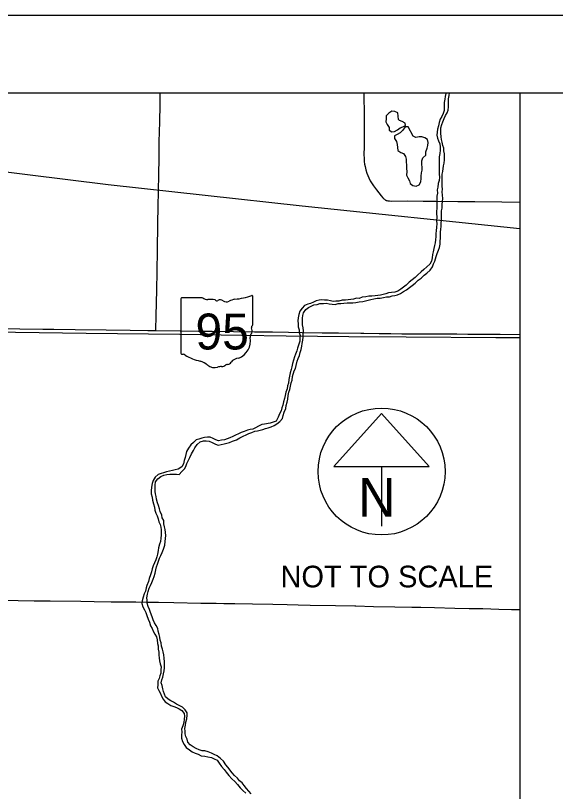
# Model space of a CAD drawing. Extents: x 0 to 680, y 0 to 440.
# Drawn here: x 401.8 to 471.5, y 339.7 to 440 of the extents above; entities that cross this region are included whole.
import ezdxf

# ---------------------------------------------------------------- set-up
doc = ezdxf.new("R2010")
doc.units = 0
for name, color, linetype in [('GM_X_County_Road', 7, 'Continuous'), ('GM_X_Major_River', 7, 'Continuous'), ('GM_X_Minor_Lake', 7, 'Continuous'), ('GM_X_State_Location', 7, 'Continuous'), ('GM_X_State_Route', 7, 'Continuous'), ('GM_X_State_Shield', 7, 'Continuous'), ('GM_X_Township_Road', 7, 'Continuous'), ('RD_X_RR_2', 7, 'Continuous'), ('SH_Border', 7, 'Continuous'), ('SH_Cut_Line', 7, 'Continuous'), ('SH_Masking', 7, 'Continuous'), ('SH_Text', 7, 'Continuous')]:
    doc.layers.add(name, color=color, linetype=linetype)

msp = doc.modelspace()

# ---------------------------------------------------------------- linework, layer by layer
at = {"layer": 'GM_X_County_Road'}
msp.add_line((454.58, 416.02), (455.63, 416.01), dxfattribs=at)
for points in [[(446.79, 430), (446.79, 429.44), (446.8, 427.47), (446.8, 426.16), (446.8, 425.17), (446.8, 423.09), (446.79, 422), (446.8, 421.55)], [(446.8, 421.55), (446.8, 421.43), (446.82, 421.13), (446.87, 420.81), (446.93, 420.49), (447.03, 420.06), (447.16, 419.64), (447.27, 419.34), (447.4, 419.04), (447.6, 418.65), (447.76, 418.37), (448, 418.01), (448.39, 417.48), (449, 416.71), (449.21, 416.46), (449.37, 416.31), (449.43, 416.25), (449.48, 416.21), (449.57, 416.16), (449.64, 416.13)], [(449.64, 416.13), (449.67, 416.12), (449.76, 416.08), (449.86, 416.06), (450.07, 416.04), (450.4, 416.03), (452.37, 416.04), (454.44, 416.02), (454.58, 416.02)], [(455.63, 416.01), (456.08, 416), (458.93, 415.98), (461.11, 415.95), (464.61, 415.91), (466.92, 415.89)], [(396.22, 364.49), (402.12, 364.41), (404.2, 364.39), (406.27, 364.36), (410.21, 364.32), (411.96, 364.29), (414.14, 364.26), (417.31, 364.23), (418.84, 364.21), (420.27, 364.18), (422.23, 364.16), (425.73, 364.09), (426.93, 364.07), (427.7, 364.05), (428.68, 364.04), (430.1, 364.01), (432.4, 363.97), (435.02, 363.92), (436.88, 363.88), (438.3, 363.85), (439.83, 363.81), (443.11, 363.75), (445.62, 363.71), (445.74, 363.71)], [(445.74, 363.71), (448.03, 363.66), (450.76, 363.61), (452.95, 363.56), (454.15, 363.54), (455.9, 363.5), (458.52, 363.44), (460.38, 363.4), (462.13, 363.36), (464.21, 363.3), (465.84, 363.27), (466.92, 363.26)]]:
    msp.add_lwpolyline(points, dxfattribs=at)
at = {"layer": 'GM_X_Major_River'}
for points in [[(457.38, 430), (457.36, 429.94), (457.27, 429.54), (457.24, 429.18), (457.14, 428.77), (457.16, 428.43), (457.15, 427.71), (457.01, 427.35), (456.83, 426.96), (456.64, 426.61), (456.5, 426.16), (456.4, 425.74), (456.3, 425.31), (456.24, 424.91), (456.22, 424.54), (456.28, 424.16), (456.43, 423.81), (456.6, 423.42), (456.63, 423.04), (456.64, 422.62), (456.58, 422.16)], [(457.06, 420.59), (457.13, 420.93), (457.18, 421.36), (457.18, 421.75), (457.18, 422.13), (457.12, 422.52), (457.12, 422.87), (456.97, 423.22), (456.91, 423.65), (456.82, 423.99), (456.76, 424.34), (456.71, 424.81), (456.71, 425.14), (456.71, 425.48), (456.84, 425.9), (456.98, 426.25), (457.16, 426.68), (457.34, 427.08), (457.52, 427.44), (457.66, 427.78), (457.7, 428.18), (457.7, 428.54), (457.69, 428.88), (457.71, 429.25), (457.78, 429.68), (457.85, 430)], [(456.58, 422.16), (456.5, 421.76), (456.51, 421.41), (456.48, 421.04), (456.5, 420.7), (456.52, 420.25), (456.49, 419.85), (456.52, 419.48), (456.54, 419.12), (456.48, 418.7), (456.37, 418.3), (456.33, 417.84), (456.26, 417.47), (456.27, 417.04), (456.21, 416.67), (456.21, 416.31), (456.19, 415.89), (456.19, 415.45), (456.19, 415.08), (456.15, 414.73), (456.17, 414.4), (456.18, 413.94), (456.17, 413.45), (456.2, 413.08), (456.15, 412.65), (456.13, 412.18), (456.09, 411.84), (456.07, 411.44), (456.03, 411.02), (456, 410.65), (455.9, 410.28), (455.82, 409.88), (455.72, 409.47), (455.64, 409.1), (455.6, 408.67), (455.5, 408.28), (455.28, 407.89), (454.91, 407.51), (454.53, 407.18), (454.16, 406.87), (453.72, 406.46), (453.39, 406.16), (453.02, 405.83), (452.64, 405.54), (452.22, 405.15), (451.89, 404.89), (451.54, 404.64), (451.15, 404.38), (450.79, 404.26), (450.33, 404.22), (449.95, 404.18), (449.61, 404.04), (449.26, 403.95), (448.93, 403.87), (448.58, 403.81), (448.24, 403.77), (447.81, 403.75), (447.44, 403.74), (447.02, 403.64), (446.57, 403.59), (446.17, 403.43), (445.82, 403.46), (445.45, 403.35), (444.75, 403.25), (444.41, 403.22), (443.97, 403.2), (443.55, 403.11), (443.17, 403.09), (442.82, 403.07), (442.46, 403.13), (442.1, 403.2), (441.71, 403.24), (441.33, 403.26), (440.99, 403.24), (440.61, 403.12), (440.28, 402.98), (439.88, 402.8), (439.53, 402.7), (439.13, 402.52), (438.83, 402.18), (438.52, 401.8), (438.37, 401.36), (438.3, 400.93), (438.24, 400.57), (438.28, 400.17), (438.31, 399.79), (438.41, 399.38), (438.44, 399.04), (438.53, 398.66), (438.5, 398.3), (438.49, 397.93), (438.4, 397.54), (438.22, 397.04), (438.1, 396.68), (437.93, 396.23), (437.81, 395.88), (437.7, 395.45), (437.58, 395.03), (437.46, 394.62), (437.38, 394.28), (437.27, 393.83)], [(437.02, 390.89), (437.1, 391.33), (437.23, 391.69), (437.29, 392.12), (437.39, 392.56), (437.5, 392.9), (437.58, 393.34), (437.78, 394.07), (437.94, 394.41), (438.04, 394.79), (438.17, 395.33), (438.29, 395.68), (438.45, 396.06), (438.56, 396.47), (438.66, 396.86), (438.75, 397.26), (438.79, 397.63), (438.91, 398.07), (438.95, 398.43), (438.95, 398.89), (438.97, 399.24), (438.92, 399.64), (438.87, 400.03), (438.84, 400.48), (438.86, 400.88), (438.91, 401.24), (438.99, 401.6), (439.28, 402), (439.63, 402.27), (439.98, 402.45), (440.32, 402.61), (440.73, 402.68), (441.1, 402.77), (441.55, 402.81), (441.9, 402.83), (442.28, 402.73), (442.7, 402.69), (443.08, 402.68), (443.46, 402.78), (443.8, 402.81), (444.17, 402.83), (444.63, 402.87), (444.97, 402.87), (445.37, 402.88), (445.73, 402.93), (446.15, 403.01), (446.63, 403.07), (446.99, 403.15), (447.32, 403.22), (447.68, 403.32), (448.08, 403.39), (448.48, 403.47), (448.9, 403.5), (449.3, 403.57), (449.72, 403.66), (450.07, 403.67), (450.43, 403.77), (450.77, 403.83), (451.14, 403.93), (451.5, 404.07), (451.88, 404.33), (452.27, 404.54), (452.66, 404.85), (453, 405.1), (453.4, 405.41), (453.81, 405.8), (454.17, 406.05), (454.57, 406.45), (454.92, 406.71), (455.32, 407.09), (455.64, 407.51), (455.78, 407.92), (455.94, 408.26), (456.1, 408.85), (456.24, 409.26), (456.4, 409.68), (456.54, 410.04), (456.65, 410.44), (456.67, 411.64), (456.68, 412.01), (456.7, 412.4), (456.78, 412.76), (456.76, 413.15), (456.81, 413.56), (456.81, 413.95), (456.81, 414.35), (456.81, 414.76), (456.87, 415.12), (456.88, 415.57), (456.93, 415.95), (456.97, 416.35), (456.95, 416.79), (456.91, 417.23), (456.95, 417.57), (456.91, 417.95), (456.89, 418.38), (456.89, 418.76), (456.87, 419.14), (456.89, 419.48), (456.97, 419.84), (457.06, 420.59)], [(437.27, 393.83), (437.18, 393.41), (437.09, 392.96), (437.03, 392.5), (436.93, 392.15), (436.87, 391.78), (436.72, 391.33), (436.63, 390.9), (436.52, 390.53), (436.42, 390.1), (436.3, 389.65), (436.19, 389.31), (436.08, 388.94), (435.89, 388.54), (435.73, 388.1), (435.47, 387.6), (435.07, 387.46), (434.66, 387.32), (433.94, 387.22), (433.58, 387.14), (433.16, 386.93), (432.8, 386.71), (432.45, 386.56), (432.11, 386.49), (431.73, 386.41), (431.34, 386.27), (430.95, 386.13), (430.59, 385.97), (430.19, 385.78), (429.84, 385.59), (429.49, 385.43), (429.13, 385.3), (428.78, 385.16), (428.39, 385.12), (428.02, 385.06), (427.65, 385.17), (427.3, 385.35), (426.92, 385.5), (426.58, 385.54), (426.2, 385.46), (425.87, 385.41), (425.48, 385.26), (425.12, 385.16), (424.77, 384.85), (424.43, 384.51), (424.12, 384.1), (423.88, 383.65), (423.77, 383.3), (423.68, 382.9), (423.57, 382.49), (423.47, 382.07), (423.26, 381.67), (422.79, 381.38), (422.39, 381.3), (422.06, 381.22), (421.68, 381.11), (421.3, 381.02), (420.92, 380.92), (420.59, 380.82), (420.23, 380.68), (419.84, 380.37), (419.59, 379.94), (419.45, 379.53), (419.36, 379.08), (419.3, 378.59), (419.33, 378.21), (419.43, 377.77), (419.49, 377.36), (419.62, 376.91), (419.76, 376.49), (419.79, 376.1), (419.92, 375.69), (420.09, 375.35), (420.21, 374.97), (420.31, 374.59), (420.47, 374.23), (420.54, 373.88), (420.6, 373.53), (420.61, 373.19), (420.6, 372.84), (420.56, 372.48), (420.5, 372.04), (420.4, 371.68), (420.27, 371.2), (420.21, 370.86), (420.11, 370.42), (420.04, 370.07), (419.91, 369.68), (419.75, 369.28), (419.57, 368.88), (419.43, 368.5), (419.34, 368.11), (419.22, 367.73), (419.07, 367.25), (418.98, 366.89), (418.77, 366.37), (418.68, 366.03), (418.57, 365.64), (418.4, 365.27), (418.26, 364.86), (418.15, 364.38)], [(419.97, 361.17), (419.73, 361.54), (419.57, 361.93), (419.43, 362.29), (419.23, 362.85), (419.1, 363.26), (418.94, 363.65), (418.81, 364.05), (418.78, 364.44), (418.75, 364.77), (418.84, 365.24), (418.94, 365.58), (419.07, 366.01), (419.23, 366.35), (419.39, 366.74), (419.57, 367.19), (419.7, 367.53), (419.82, 367.93), (419.92, 368.37), (420.02, 368.78), (420.12, 369.13), (420.24, 369.48), (420.4, 369.88), (420.55, 370.25), (420.73, 370.61), (420.91, 371.03), (421.06, 371.55), (421.12, 372.03), (421.16, 372.42), (421.19, 372.83), (421.17, 373.22), (421.1, 373.59), (421.02, 373.93), (420.96, 374.3), (420.96, 374.77), (420.75, 375.11), (420.67, 375.44), (420.49, 375.9), (420.39, 376.26), (420.27, 376.68), (420.13, 377.04), (420, 377.5), (419.95, 377.84), (419.85, 378.18), (419.81, 378.51), (419.81, 378.87), (419.83, 379.3), (419.88, 379.74), (420.16, 380.12), (420.58, 380.45), (420.96, 380.61), (421.33, 380.69), (421.73, 380.73), (422.58, 380.72), (422.94, 380.69), (423.28, 381.07), (423.62, 381.41), (423.8, 381.75), (423.92, 382.1), (424.14, 382.53), (424.31, 382.91), (424.5, 383.36), (424.76, 383.78), (424.97, 384.12), (425.27, 384.56), (425.65, 384.91), (426.05, 385.04), (426.42, 385.03), (426.79, 385.01), (427.19, 384.84), (427.61, 384.6), (427.97, 384.48), (428.33, 384.56), (428.73, 384.64), (429.1, 384.73), (429.44, 384.83), (429.8, 384.99), (430.32, 385.16), (430.77, 385.42), (431.21, 385.66), (431.58, 385.84), (431.92, 385.98), (432.33, 386.14), (432.7, 386.3), (433.04, 386.33), (433.38, 386.42), (433.72, 386.52), (434.09, 386.62), (434.42, 386.71), (434.82, 386.85), (435.18, 387.04), (435.55, 387.26), (435.94, 387.55), (436.26, 387.94), (436.36, 388.33), (436.49, 388.77), (436.7, 389.23), (436.74, 389.62), (436.87, 390.03), (436.97, 390.45), (437.02, 390.89)], [(418.15, 364.38), (418.1, 364.01), (418.24, 363.58), (418.46, 363.2), (418.62, 362.87), (418.77, 362.46), (418.92, 362.02), (419.1, 361.62), (419.24, 361.12), (419.42, 360.78), (419.59, 360.45), (419.79, 360.06), (420, 359.72), (420.1, 359.34), (420.13, 358.88), (420.2, 358.54), (420.23, 358.11), (420.29, 357.72), (420.31, 357.35), (420.36, 356.99), (420.39, 356.6), (420.49, 356.25), (420.6, 355.84), (420.56, 355.45), (420.55, 355.04), (420.44, 354.68), (420.34, 354.33), (420.17, 353.98), (420.15, 353.51), (420.13, 353.12), (420.29, 352.77), (420.51, 352.41), (420.65, 352.07), (420.86, 351.68), (421.1, 351.32), (421.46, 351.11), (421.85, 350.84), (422.22, 350.72), (422.57, 350.59), (422.94, 350.41), (423.28, 350.2), (423.58, 349.82), (423.63, 349.49), (423.59, 349.1), (423.53, 348.67), (423.42, 348.22), (423.24, 347.78), (423.27, 347.45), (423.21, 347.01), (423.23, 346.64), (423.36, 346.19), (423.58, 345.8), (423.85, 345.44), (424.27, 345.1), (424.62, 344.85), (424.99, 344.67), (425.36, 344.54), (425.78, 344.34), (426.26, 344.3), (426.63, 344.2), (427.08, 344.11), (427.46, 343.97), (427.85, 343.77), (428.07, 343.39), (428.38, 342.96), (428.72, 342.58), (428.99, 342.24), (429.32, 341.82), (429.72, 341.39), (430.1, 341.01), (430.47, 340.64), (430.82, 340.22), (431.15, 339.85), (431.53, 339.51)], [(432.21, 339.42), (431.93, 339.79), (431.64, 340.14), (431.32, 340.49), (431.07, 340.87), (430.72, 341.1), (430.46, 341.45), (430.06, 341.82), (429.79, 342.16), (429.19, 342.86), (428.95, 343.2), (428.63, 343.66), (428.28, 344.01), (427.84, 344.35), (427.43, 344.52), (427.08, 344.71), (426.69, 344.86), (426.25, 344.97), (425.9, 345), (425.51, 345.13), (425.1, 345.3), (424.73, 345.49), (424.36, 345.76), (424.04, 346.12), (423.94, 346.49), (423.78, 346.84), (423.71, 347.2), (423.69, 347.54), (423.67, 347.88), (423.75, 348.3), (423.8, 348.7), (423.93, 349.13), (423.95, 349.59), (423.95, 349.92), (423.72, 350.27), (423.35, 350.64), (423.01, 350.79), (422.6, 351), (422.21, 351.26), (421.86, 351.45), (421.49, 351.66), (421.14, 351.98), (421.03, 352.33), (420.92, 352.67), (420.81, 353.02), (420.71, 353.43), (420.62, 353.78), (420.68, 354.18), (420.81, 354.53), (420.92, 354.92), (421, 355.34), (421.04, 355.71), (421.05, 356.12), (421.03, 356.47), (420.98, 356.98), (420.95, 357.39), (420.85, 357.77), (420.79, 358.13), (420.66, 358.52), (420.62, 358.95), (420.47, 359.31), (420.43, 359.66), (420.33, 360.02), (420.21, 360.45), (420.17, 360.78), (419.97, 361.17)]]:
    msp.add_lwpolyline(points, dxfattribs=at)
at = {"layer": 'GM_X_Minor_Lake'}
for points in [[(451.16, 427.41), (450.77, 427.61), (450.41, 427.63), (450.01, 427.38), (449.67, 427.03), (449.65, 426.67), (449.62, 426.28), (449.79, 425.93), (450.05, 425.54), (450.03, 425.19), (450.37, 424.97), (450.72, 425.02), (451.11, 425.23), (451.47, 425.47), (451.82, 425.61), (452.15, 425.77), (452.09, 426.1), (451.72, 426.3), (451.38, 426.44), (451.26, 426.56)], [(451.26, 426.56), (451.16, 427.41)], [(452.51, 425.62), (452.1, 425.62), (451.81, 425.19), (451.47, 424.83), (451.06, 424.64), (450.72, 424.45), (450.74, 424.09), (451, 423.73), (451.09, 423.35), (451.18, 422.54), (451.54, 422.31), (451.89, 422.16), (452.15, 421.79), (452.23, 421.44), (452.25, 421.07), (452.28, 420.71), (452.27, 420.22), (452.31, 419.83), (452.29, 419.36), (452.45, 419.03), (452.65, 418.66), (452.76, 418.29), (453.1, 418.03), (453.51, 417.93), (453.9, 418.11), (454.14, 418.5), (454.17, 418.92), (454.17, 419.26), (454.22, 419.66), (454.29, 420.03), (454.3, 420.39), (454.27, 420.77), (454.27, 421.21), (454.4, 421.61), (454.77, 421.97), (454.8, 422.37), (454.95, 422.85), (455.05, 423.21), (455.1, 423.61), (455, 424), (454.64, 424.19), (454.26, 424.31), (453.91, 424.31), (453.5, 424.26), (453.16, 424.43)], [(453.16, 424.43), (452.51, 425.62)]]:
    msp.add_lwpolyline(points, dxfattribs=at)
at = {"layer": 'GM_X_State_Route'}
for points in [[(393.94, 399.66), (398.76, 399.59), (402.37, 399.53), (405.32, 399.49), (406.74, 399.47), (409.48, 399.43), (413.52, 399.39), (416.58, 399.34), (418.88, 399.31), (419.92, 399.3), (423.04, 399.27), (425.44, 399.23), (427.19, 399.2), (429.93, 399.16), (432.66, 399.13), (434.96, 399.11), (437.04, 399.07), (438.79, 399.05), (441.41, 399.02), (443.49, 398.99), (446.39, 398.94)], [(446.39, 398.94), (446.77, 398.94), (448.74, 398.92), (450.27, 398.91), (451.69, 398.89), (452.79, 398.89), (454.43, 398.88), (456.72, 398.85), (458.8, 398.86), (460.22, 398.84), (462.41, 398.83), (464.38, 398.82), (466.92, 398.8)]]:
    msp.add_lwpolyline(points, dxfattribs=at)
at = {"layer": 'GM_X_State_Shield'}
for p, q in [((423.15, 403.4), (423.15, 396.36)), ((425.96, 403.52), (423.24, 403.52)), ((432.43, 400.01), (432.43, 403.7)), ((432.43, 400.01), (432.43, 400.01))]:
    msp.add_line(p, q, dxfattribs=at)
for centre, radius, start, end in [((423.26, 403.42), 0.108, 98.1301, 188.1301), ((426.61, 404.34), 1.04, 231.6195, 271.1119), ((426.95, 399.57), 3.74, 80.4867, 94.9883), ((427.8, 403.45), 0.301, 219.7921, 297.1024), ((428.24, 402.64), 0.626, 54.4667, 119.1411), ((429.05, 403.76), 0.753, 233.8562, 294.8282), ((430.38, 401.37), 1.98, 97.3462, 120.7689), ((429.12, 413.13), 9.84, 275.8445, 288.9065), ((432.33, 403.71), 0.103, 351.8621, 97.738), ((432.41, 399.74), 0.16, 107.944, 210.337), ((431.39, 399.28), 0.96, 340.033, 23.6496), ((432.32, 400), 0.111, 289.6038, 7.7341), ((429.68, 398), 2.46, 292.3089, 8.9858), ((432.8, 398.47), 0.698, 136.8065, 186.9296), ((423.26, 396.34), 0.108, 171.9584, 258.3066), ((423.27, 397.06), 0.828, 267.339, 280.6039), ((423.44, 395.95), 0.298, 29.7484, 93.2717), ((427.21, 402.28), 7.11, 240.4129, 257.1985), ((425.09, 393.19), 2.22, 47.1842, 75.836), ((429.01, 395.68), 0.795, 282.8732, 323.2771), ((430.71, 394.38), 1.35, 94.4031, 142.5768), ((427.5, 395.92), 1.41, 230.7004, 286.2918), ((428.31, 393.48), 1.16, 85.6951, 111.2099), ((428.42, 395.39), 0.752, 268.777, 315.5493), ((429.1, 394.71), 0.212, 65.7517, 132.6484)]:
    msp.add_arc(centre, radius, start, end, dxfattribs=at)
at = {"layer": 'GM_X_Township_Road'}
for points in [[(420.41, 425.91), (420.47, 428.81), (420.49, 430)], [(419.92, 399.3), (419.92, 399.52), (419.96, 401.05), (420, 403.02), (420.03, 404.44), (420.12, 409.58), (420.18, 413.18), (420.22, 415.26), (420.26, 417.34), (420.29, 419.41), (420.33, 421.6), (420.36, 423.35), (420.4, 425.31), (420.41, 425.91)]]:
    msp.add_lwpolyline(points, dxfattribs=at)
at = {"layer": 'RD_X_RR_2'}
for points in [[(313.66, 430), (323.68, 428.91), (333.73, 427.55), (360.02, 424.5), (387.32, 421.44), (413.77, 418.16), (438.79, 415.43), (466.92, 412.47)], [(466.92, 398.36), (463.84, 398.36), (452.25, 398.42), (444.84, 398.49), (436.74, 398.59), (431.01, 398.67), (423, 398.78), (410.9, 398.93), (383.5, 399.29), (378.63, 399.34), (358.23, 399.54), (332.13, 399.75), (318.98, 399.86)]]:
    msp.add_lwpolyline(points, dxfattribs=at)
at = {"layer": 'SH_Border'}
msp.add_lwpolyline([(30, 430), (670, 430), (670, 10), (30, 10)], close=True, dxfattribs=at)
at = {"layer": 'SH_Cut_Line'}
msp.add_lwpolyline([(0, 0), (680, 0), (680, 440), (0, 440)], close=True, dxfattribs=at)
at = {"layer": 'SH_Masking'}
msp.add_circle((449.06, 381.08), 8.2, dxfattribs=at)
at = {"layer": 'SH_Text'}
for p, q in [((449.06, 388.56), (442.91, 381.73)), ((455.21, 381.73), (449.06, 388.56)), ((442.91, 381.73), (455.21, 381.73)), ((449.06, 381.73), (449.06, 374))]:
    msp.add_line(p, q, dxfattribs=at)
msp.add_lwpolyline([(30, 430), (466.92, 430), (466.92, 291.27), (342.9, 138.72), (30, 138.72)], close=True, dxfattribs=at)
msp.add_circle((449.06, 381.08), 8.2, dxfattribs=at)

# ---------------------------------------------------------------- texts
at = {"layer": 'GM_X_State_Location'}
for s in ['s', 'r']:
    msp.add_text(s, height=0.00667, dxfattribs=at).set_placement((460.05, 398.05))
msp.add_text('95', height=0.00667, rotation=0, dxfattribs=at).set_placement((458.37, 397.57))
at = {"layer": 'GM_X_State_Shield'}
msp.add_text('95', height=4.641, dxfattribs=at).set_placement((425.03, 396.85))
at = {"layer": 'SH_Text'}
for s, height, p in [('N', 5, (446.03, 375.25)), ('NOT TO SCALE', 2.8, (436.01, 366.11))]:
    msp.add_text(s, height=height, dxfattribs=at).set_placement(p)

doc.saveas('drawing.dxf')
